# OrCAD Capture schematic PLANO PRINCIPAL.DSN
size A
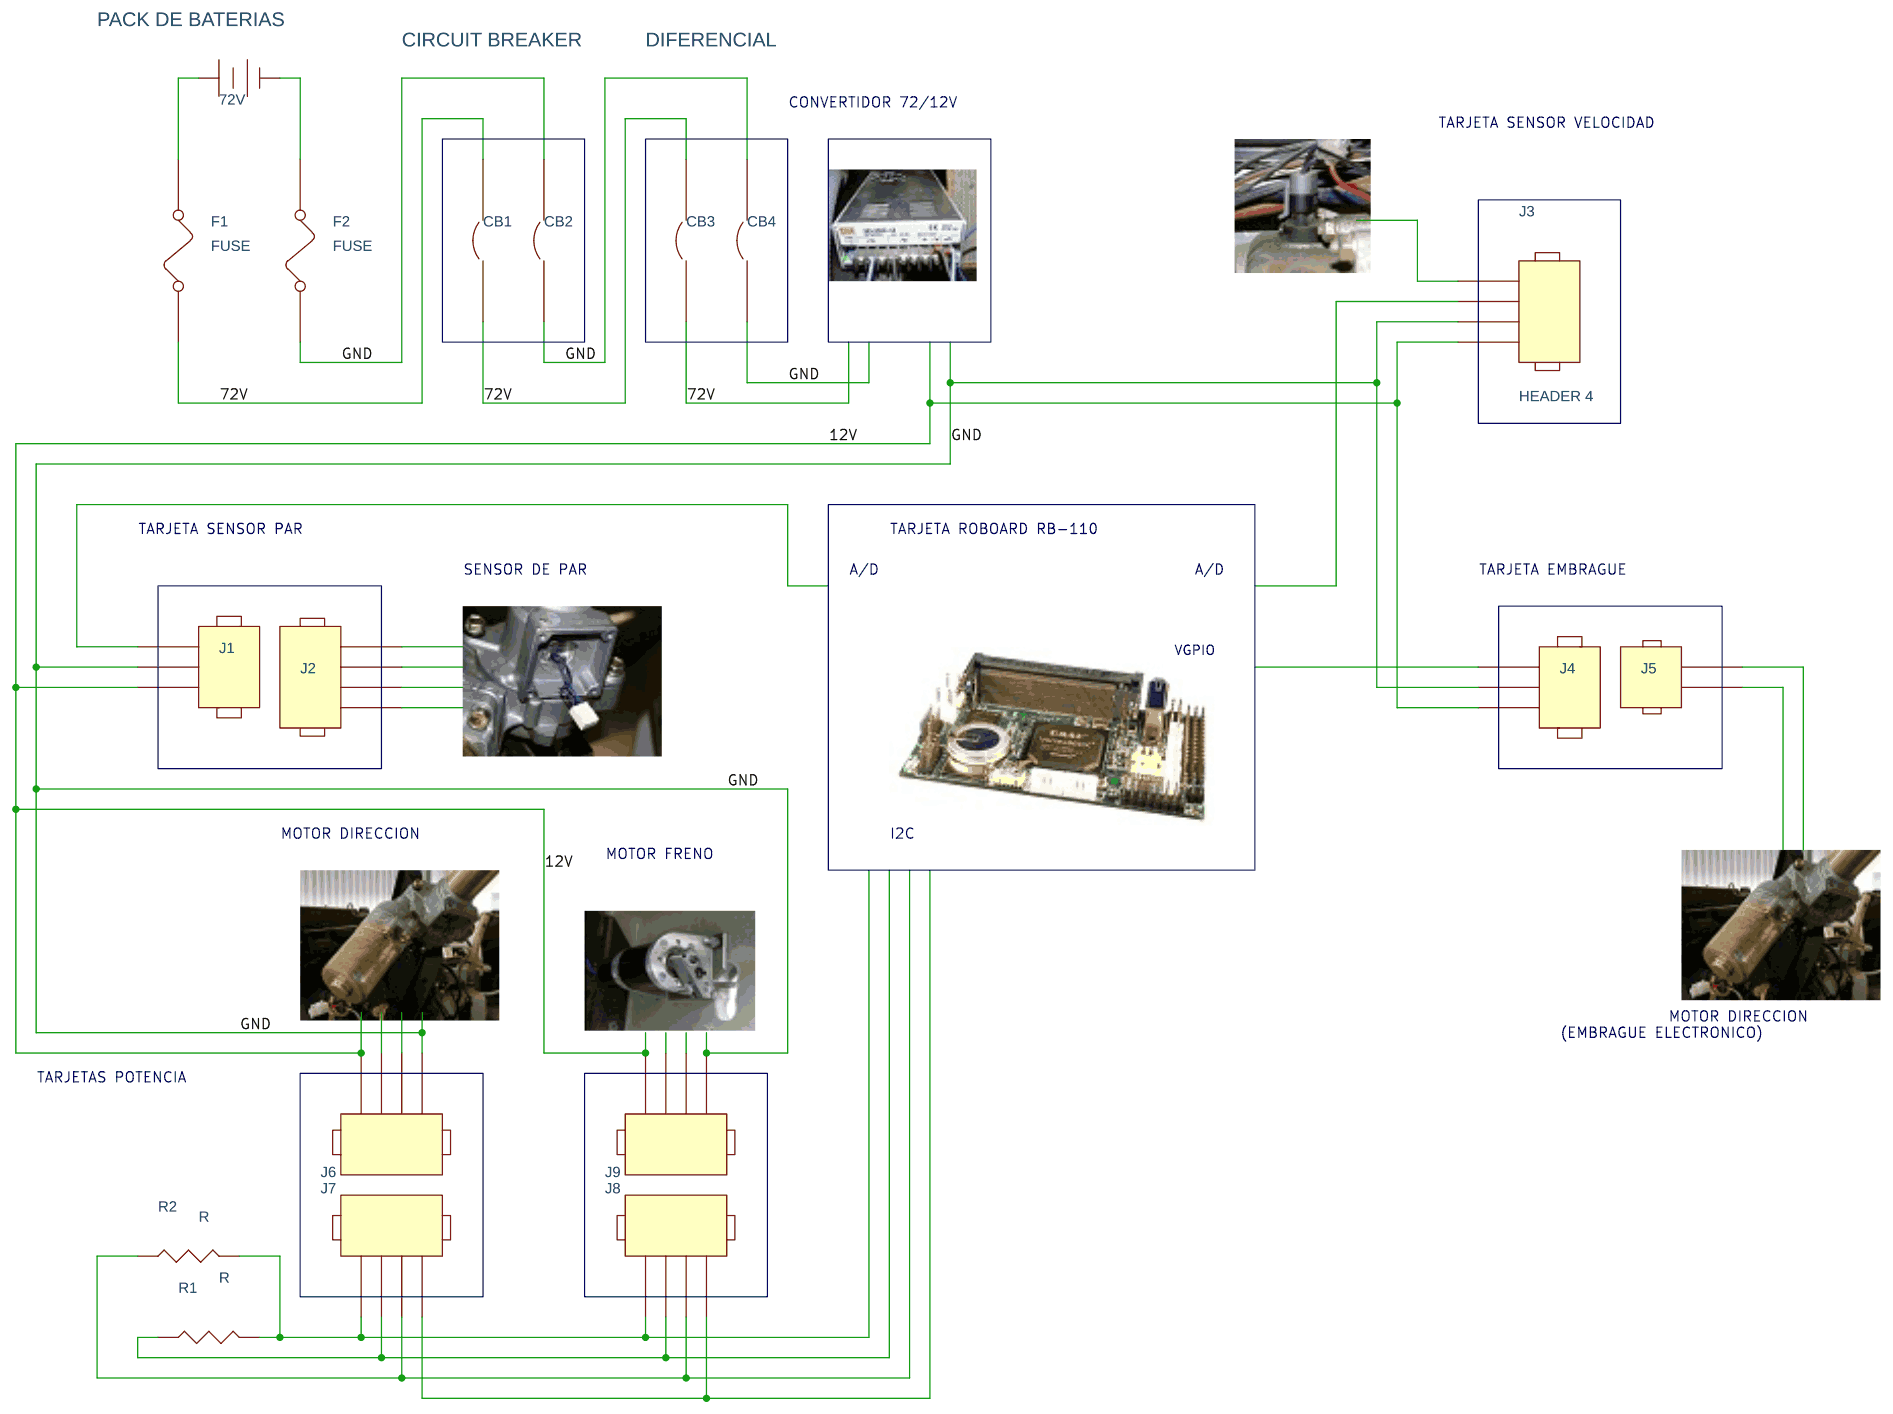
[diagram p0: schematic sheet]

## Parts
72V  PACK DE BATERIAS
CB1  CIRCUIT BREAKER
CB2  CIRCUIT BREAKER
CB3  DIFERENCIAL
CB4  CIRCUIT BREAKER
F1  FUSE
F2  FUSE
J1  HEADER 3
J2  HEADER 4
J3  HEADER 4
J4  HEADER 3
J5  HEADER 2
J6  HEADER 4
J7  HEADER 4
J8  HEADER 4
J9  HEADER 4
R1  R
R2  R

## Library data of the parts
72V = BATTERY
CB1-CB4 = CIRCUIT_BREAKER
F1 F2 = FUSE
J1 J4 = HEADER_3
J2 J3 J6-J9 = HEADER_4
J5 = HEADER_2
R1 R2 = R

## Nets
12V: J1.1 J3.1 J4.1 J7.1 J8.1
72V: CB1.1 CB1.2 CB3.1 CB3.2 F1.1
GND: CB2.1 CB2.2 CB4.1 CB4.2 F2.1 J1.2 J3.2 J4.2 J7.4 J8.4
N00181: 72V.1(+) F1.2
N00188: 72V.2(-) F2.2
N01068: J6.4 J9.4 R1.2 R2.2
N01086: J6.3 J9.3 R1.1
N01132: J6.2 J9.2 R2.1
N01175: J6.1 J9.1

Not connected (* = marked no-connect by the designer): J1 3; J2 1 2 3 4; J3 3 4; J4 3; J5 1 2; J7 2 3; J8 2 3

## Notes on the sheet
- CONVERTIDOR 72/12V
- TARJETA SENSOR VELOCIDAD
- TARJETA SENSOR PAR
- TARJETA ROBOARD RB-110
- SENSOR DE PAR
- A/D
- A/D
- TARJETA EMBRAGUE
- VGPIO
- MOTOR DIRECCION
- I2C
- MOTOR FRENO
- MOTOR DIRECCION
  (EMBRAGUE ELECTRONICO)
- TARJETAS POTENCIA
